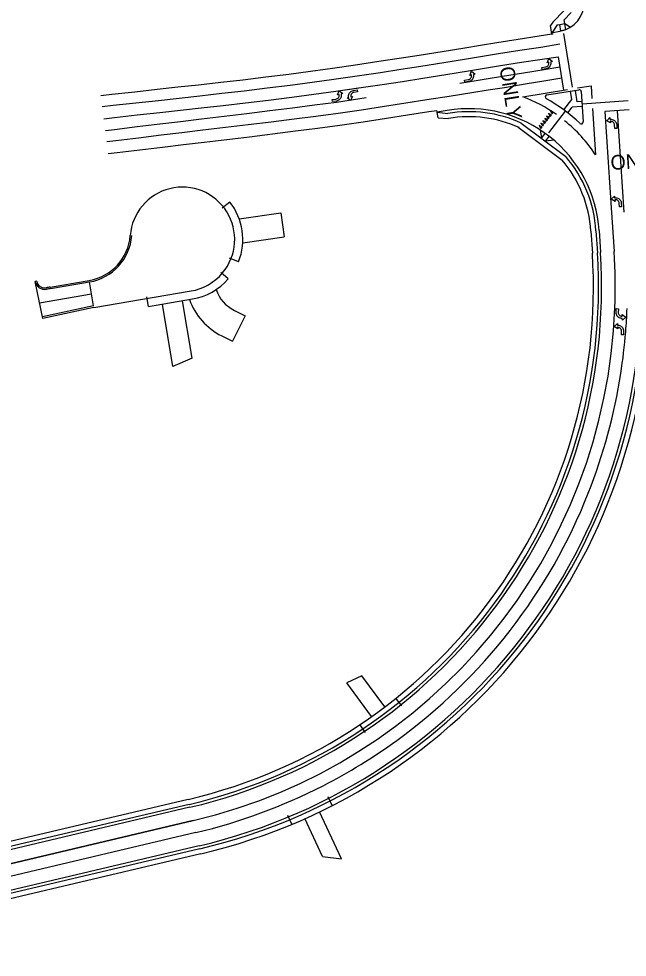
# Model space of a CAD drawing. Extents: x 979036 to 996074, y 1836928 to 1845163.
# Drawn here: x 982073 to 982672, y 1841767 to 1842691 of the extents above; entities that cross this region are included whole.
import ezdxf

# ---------------------------------------------------------------- set-up
doc = ezdxf.new("R2010")
doc.units = 0
for name, color, linetype in [('R_Proposed Road', 7, 'Continuous'), ('STRIPE_White Crosswalk', 7, 'Continuous'), ('STRIPE_White Stopbar', 7, 'Continuous'), ('STRIPE_White Turn Arrow', 7, 'Continuous'), ('STRIPE_WHITE_10_30 SKIP', 7, 'Continuous'), ('STRIPE_White_6in', 7, 'Continuous'), ('STRIPE_White_Dashed', 7, 'Continuous'), ('STRIPE_White_ONLY', 7, 'Continuous'), ('STRIPE_White_Yield Tri', 7, 'Continuous'), ('STRIPE_Yellow Dbl 6in', 7, 'Continuous'), ('STRIPE_Yellow_10_30 SKIP', 7, 'Continuous'), ('STRIPE_Yellow_45_Diag_8in', 7, 'Continuous')]:
    doc.layers.add(name, color=color, linetype=linetype)

msp = doc.modelspace()

# ---------------------------------------------------------------- linework, layer by layer
at = {"layer": 'R_Proposed Road'}
for p, q in [((982621.5, 1842711.53), (982599.06, 1842688.03)), ((982616.91, 1842697.36), (982610.13, 1842690.24)), ((982599.06, 1842688.03), (982596.68, 1842684.43)), ((982611.69, 1842680.55), (982610.13, 1842690.24)), ((982598, 1842676.16), (982596.68, 1842684.43)), ((982597.76, 1842677.64), (982598.96, 1842677.84)), ((982603.23, 1842685.27), (982598.22, 1842677.72)), ((982598.96, 1842677.84), (982605.77, 1842678.93)), ((982603.23, 1842685.27), (982605.8, 1842685.68)), ((982605.8, 1842685.68), (982610.74, 1842686.47)), ((982606.85, 1842679.13), (982605.8, 1842685.68)), ((982606.75, 1842679.76), (982611.69, 1842680.55)), ((982610.74, 1842686.47), (982616.37, 1842682.91)), ((982598, 1842676.16), (982599.19, 1842676.35)), ((982593.23, 1842616.23), (982624.7, 1842621.27)), ((982617.66, 1842611.73), (982616.34, 1842619.93)), ((982623.07, 1842609.57), (982621.28, 1842620.72)), ((982627.01, 1842619.43), (982628.95, 1842589.81)), ((982609.69, 1842601.57), (982617.66, 1842611.73)), ((982613.68, 1842598.55), (982618.14, 1842604.24)), ((982627.96, 1842604.88), (982618.14, 1842604.24)), ((982627.64, 1842609.87), (982623.07, 1842609.57)), ((982485.98, 1842593.61), (982484.81, 1842600.89)), ((982494.95, 1842600.89), (982485.05, 1842599.39)), ((982485.05, 1842599.39), (982495.45, 1842597.93)), ((982485.98, 1842593.61), (982496.28, 1842593)), ((982567.88, 1842588.55), (982611.69, 1842555.65)), ((982564.88, 1842584.55), (982608.24, 1842551.99)), ((982586.54, 1842581.74), (982587.79, 1842573.6)), ((982587.79, 1842573.6), (982591.49, 1842578.33)), ((982591.79, 1842570.6), (982595.49, 1842575.32)), ((982600.12, 1842571.51), (982591.79, 1842570.6)), ((982280.91, 1842510.72), (982273.45, 1842504.84)), ((982290.11, 1842494.19), (982330.98, 1842500.16)), ((982330.98, 1842500.16), (982334.45, 1842476.41)), ((982293.58, 1842470.44), (982334.45, 1842476.41)), ((982636.48, 1842482.02), (982637.89, 1842460.45)), ((982641.47, 1842482.34), (982642.88, 1842460.77)), ((982644.47, 1842482.54), (982645.88, 1842460.97)), ((982289.49, 1842451.97), (982280.66, 1842455.47)), ((982279.28, 1842435.09), (982272.08, 1842441.29)), ((982090.73, 1842432.69), (982089.26, 1842432.39)), ((982096.68, 1842396.14), (982089.26, 1842432.39)), ((982090.76, 1842432.58), (982090.73, 1842432.69)), ((982104.07, 1842427.01), (982142.55, 1842433.53)), ((982104.32, 1842425.54), (982142.8, 1842432.05)), ((982146.81, 1842408.39), (982142.8, 1842432.05)), ((982147.06, 1842406.91), (982242.77, 1842423.12)), ((982200.73, 1842407.88), (982199.14, 1842417.25)), ((982200.73, 1842407.88), (982244.11, 1842415.23)), ((982224.92, 1842348.88), (982214.53, 1842410.22)), ((982243.86, 1842356.83), (982234.25, 1842413.56)), ((982146.81, 1842408.39), (982096.38, 1842397.61)), ((982147.12, 1842406.92), (982096.69, 1842396.14)), ((982285.41, 1842403.98), (982295.95, 1842398.76)), ((982295.95, 1842398.76), (982283.51, 1842373.67)), ((982272.97, 1842378.9), (982283.51, 1842373.67)), ((982243.86, 1842356.83), (982224.92, 1842348.88)), ((982410.97, 1842044.14), (982396.28, 1842037.11)), ((982433.45, 1842013.45), (982410.97, 1842044.14)), ((982420.54, 1842004), (982396.28, 1842037.11)), ((982450.12, 1842014.38), (982444.5, 1842022.05)), ((982414.63, 1841988.38), (982409.01, 1841996.05)), ((982239.83, 1841922.37), (981808.02, 1841820.47)), ((982381.78, 1841916.37), (982377.78, 1841924.99)), ((982240.98, 1841917.5), (981809.17, 1841815.6)), ((982241.67, 1841914.58), (981809.86, 1841812.68)), ((982341.87, 1841897.86), (982337.87, 1841906.48)), ((982372.01, 1841866.14), (982354.72, 1841903.41)), ((982390.77, 1841863.72), (982369.24, 1841910.15)), ((982250.63, 1841876.63), (981818.82, 1841774.72)), ((982251.32, 1841873.71), (981819.5, 1841771.8)), ((982252.47, 1841868.84), (981820.65, 1841766.94)), ((982372.01, 1841866.14), (982390.77, 1841863.72))]:
    msp.add_line(p, q, dxfattribs=at)
for centre, radius, start, end in [((982601.25, 1842707.07), 28.5, 279.12753, 3.73532), ((982593.55, 1842614.25), 2, 99.11059, 241.10715), ((982625.02, 1842619.3), 2, 3.73532, 99.11059), ((982516.24, 1842474.17), 158, 46.21643, 61.10715), ((982516.24, 1842474.17), 128.5, 3.73532, 99.53629), ((982516.24, 1842474.17), 125.5, 65.70107, 99.53629), ((982516.24, 1842474.17), 120.5, 65.70107, 99.53629), ((982626.95, 1842589.68), 2, 226.21643, 3.73532), ((982516.24, 1842474.17), 120.5, 3.73532, 40.22822), ((982516.24, 1842474.17), 125.5, 3.73532, 40.48819), ((982234.18, 1842473.89), 51.5, 320.1465, 175.72415), ((982234.18, 1842473.89), 59.5, 338.38202, 38.24074), ((982134.45, 1842481.35), 48.5, 279.61069, 355.72415), ((982134.45, 1842481.35), 50, 279.61069, 355.72415), ((982120.82, 1842426.69), 518.17, 283.27832, 3.73532), ((982120.82, 1842426.69), 523.17, 283.27832, 3.73532), ((982120.82, 1842426.69), 526.17, 283.27832, 3.73532), ((982120.82, 1842426.69), 565.17, 283.27832, 3.73532), ((982120.82, 1842426.69), 568.17, 283.27832, 3.73532), ((982120.82, 1842426.69), 573.17, 283.27832, 3.73532), ((982234.18, 1842473.89), 51.5, 279.61069, 320.1465), ((982098.59, 1842434.18), 9.5, 191.55654, 280.20735), ((982098.59, 1842434.18), 8, 191.55654, 280.20735), ((982234.18, 1842473.89), 59.5, 279.61069, 319.29798), ((982170.09, 1842037.09), 395.47, 99.61069, 100.20735), ((982170.09, 1842037.09), 393.97, 99.61069, 100.20735), ((982301.4, 1842436.24), 36, 199.00806, 243.62815), ((982301.4, 1842436.24), 64, 199.6413, 243.62815)]:
    msp.add_arc(centre, radius, start, end, dxfattribs=at)
at = {"layer": 'STRIPE_White Crosswalk'}
for p, q in [((982618.24, 1842623.89), (982609.78, 1842676.65)), ((982673.08, 1842610.34), (982627.82, 1842607.14)), ((982595.13, 1842578.93), (982611.45, 1842600.26))]:
    msp.add_line(p, q, dxfattribs=at)
at = {"layer": 'STRIPE_White Stopbar'}
for p, q in [((982604.32, 1842653.88), (982609.61, 1842620.88)), ((982674.29, 1842601.39), (982650.34, 1842599.83))]:
    msp.add_line(p, q, dxfattribs=at)
at = {"layer": 'STRIPE_White Turn Arrow'}
for points in [[(982593.34, 1842647.95), (982595.05, 1842651.97), (982598.5, 1842649.3), (982596.88, 1842648.88), (982596.99, 1842648.22), (982597.05, 1842647.65), (982597.01, 1842646.83), (982596.8, 1842645.84), (982596.51, 1842645.05), (982596.06, 1842644.38), (982595.55, 1842643.6), (982594.94, 1842643.09), (982594.27, 1842642.55), (982593.38, 1842642.13), (982592.44, 1842641.83), (982588.58, 1842641.27), (982588.28, 1842643.25), (982591.84, 1842643.8), (982592.51, 1842643.96), (982593.2, 1842644.29), (982593.91, 1842644.79), (982594.45, 1842645.45), (982594.62, 1842645.78), (982594.89, 1842646.45), (982595.01, 1842647.24), (982595.01, 1842647.99), (982594.95, 1842648.37)], [(982517.2, 1842635.45), (982518.9, 1842639.47), (982522.35, 1842636.8), (982520.74, 1842636.38), (982520.85, 1842635.72), (982520.91, 1842635.14), (982520.87, 1842634.33), (982520.66, 1842633.34), (982520.36, 1842632.55), (982519.92, 1842631.88), (982519.41, 1842631.09), (982518.79, 1842630.59), (982518.12, 1842630.05), (982517.24, 1842629.63), (982516.29, 1842629.32), (982512.43, 1842628.77), (982512.14, 1842630.75), (982515.69, 1842631.29), (982516.36, 1842631.45), (982517.05, 1842631.79), (982517.76, 1842632.28), (982518.31, 1842632.95), (982518.48, 1842633.28), (982518.75, 1842633.95), (982518.87, 1842634.74), (982518.86, 1842635.48), (982518.81, 1842635.87)], [(982386.95, 1842616.32), (982388.7, 1842620.31), (982392.12, 1842617.61), (982390.5, 1842617.2), (982390.6, 1842616.54), (982390.65, 1842615.97), (982390.61, 1842615.15), (982390.38, 1842614.17), (982390.08, 1842613.38), (982389.63, 1842612.71), (982389.11, 1842611.93), (982388.49, 1842611.44), (982387.82, 1842610.9), (982386.92, 1842610.5), (982385.98, 1842610.2), (982382.11, 1842609.69), (982381.84, 1842611.67), (982385.39, 1842612.18), (982386.07, 1842612.33), (982386.76, 1842612.66), (982387.48, 1842613.14), (982388.03, 1842613.8), (982388.2, 1842614.13), (982388.48, 1842614.8), (982388.61, 1842615.59), (982388.61, 1842616.33), (982388.56, 1842616.72)], [(982401.57, 1842614.59), (982399.81, 1842610.6), (982396.4, 1842613.33), (982398.02, 1842613.72), (982397.92, 1842614.38), (982397.87, 1842614.96), (982397.92, 1842615.78), (982398.15, 1842616.76), (982398.46, 1842617.54), (982398.91, 1842618.21), (982399.44, 1842618.99), (982400.06, 1842619.48), (982400.74, 1842620.01), (982401.63, 1842620.41), (982402.58, 1842620.7), (982406.45, 1842621.2), (982406.71, 1842619.21), (982403.15, 1842618.72), (982402.47, 1842618.57), (982401.78, 1842618.25), (982401.06, 1842617.77), (982400.51, 1842617.11), (982400.33, 1842616.78), (982400.05, 1842616.12), (982399.92, 1842615.33), (982399.91, 1842614.58), (982399.96, 1842614.2)], [(982655.85, 1842588.58), (982652.02, 1842590.66), (982655, 1842593.84), (982655.27, 1842592.2), (982655.93, 1842592.24), (982656.51, 1842592.24), (982657.32, 1842592.13), (982658.28, 1842591.83), (982659.04, 1842591.46), (982659.67, 1842590.95), (982660.4, 1842590.37), (982660.84, 1842589.71), (982661.32, 1842588.99), (982661.65, 1842588.07), (982661.87, 1842587.1), (982662.05, 1842583.2), (982660.05, 1842583.1), (982659.85, 1842586.69), (982659.75, 1842587.37), (982659.49, 1842588.09), (982659.06, 1842588.84), (982658.45, 1842589.45), (982658.13, 1842589.65), (982657.5, 1842589.98), (982656.72, 1842590.18), (982655.98, 1842590.24), (982655.59, 1842590.22)], [(982660.41, 1842511.35), (982656.57, 1842513.43), (982659.56, 1842516.61), (982659.82, 1842514.97), (982660.49, 1842515.02), (982661.07, 1842515.02), (982661.88, 1842514.9), (982662.84, 1842514.6), (982663.6, 1842514.23), (982664.23, 1842513.72), (982664.96, 1842513.14), (982665.4, 1842512.48), (982665.88, 1842511.76), (982666.21, 1842510.84), (982666.42, 1842509.87), (982666.61, 1842505.97), (982664.61, 1842505.87), (982664.4, 1842509.46), (982664.31, 1842510.14), (982664.04, 1842510.86), (982663.62, 1842511.62), (982663, 1842512.22), (982662.69, 1842512.42), (982662.05, 1842512.75), (982661.28, 1842512.95), (982660.53, 1842513.01), (982660.14, 1842513)], [(982667.13, 1842399.8), (982670.75, 1842397.36), (982667.47, 1842394.48), (982667.37, 1842396.15), (982666.7, 1842396.16), (982666.12, 1842396.22), (982665.33, 1842396.41), (982664.4, 1842396.81), (982663.68, 1842397.25), (982663.11, 1842397.81), (982662.43, 1842398.46), (982662.06, 1842399.16), (982661.65, 1842399.92), (982661.41, 1842400.87), (982661.29, 1842401.86), (982661.49, 1842405.76), (982663.49, 1842405.66), (982663.35, 1842402.07), (982663.37, 1842401.38), (982663.57, 1842400.64), (982663.92, 1842399.85), (982664.47, 1842399.19), (982664.76, 1842398.96), (982665.36, 1842398.57), (982666.12, 1842398.3), (982666.85, 1842398.16), (982667.24, 1842398.14)], [(982662.87, 1842385.7), (982659.24, 1842388.12), (982662.51, 1842391.02), (982662.62, 1842389.35), (982663.29, 1842389.34), (982663.87, 1842389.29), (982664.66, 1842389.1), (982665.59, 1842388.71), (982666.31, 1842388.27), (982666.89, 1842387.71), (982667.57, 1842387.06), (982667.94, 1842386.36), (982668.36, 1842385.61), (982668.6, 1842384.66), (982668.72, 1842383.67), (982668.55, 1842379.77), (982666.55, 1842379.85), (982666.67, 1842383.45), (982666.64, 1842384.14), (982666.45, 1842384.88), (982666.09, 1842385.67), (982665.54, 1842386.32), (982665.24, 1842386.55), (982664.64, 1842386.94), (982663.88, 1842387.21), (982663.15, 1842387.34), (982662.76, 1842387.36)]]:
    msp.add_lwpolyline(points, close=True, dxfattribs=at)
at = {"layer": 'STRIPE_WHITE_10_30 SKIP'}
msp.add_lwpolyline([(982607.71, 1842632.68), (982592.2, 1842630.18), (982571.76, 1842626.78), (982551.24, 1842623.36), (982535.19, 1842620.83), (982519.2, 1842618.31), (982497.03, 1842614.79), (982474.85, 1842611.27), (982454.08, 1842608.03), (982433.31, 1842604.79), (982410.44, 1842601.36), (982387.5, 1842597.92), (982365.75, 1842595.12), (982344.1, 1842592.33), (982321.54, 1842589.5), (982298.95, 1842586.66), (982276.57, 1842584.03), (982254.25, 1842581.41), (982233.77, 1842578.94), (982213.27, 1842576.47), (982191, 1842573.77), (982168.7, 1842571.07), (982159.63, 1842570.02)], dxfattribs=at)
at = {"layer": 'STRIPE_White_6in'}
for p, q in [((982623.43, 1842623.09), (982636.66, 1842625.22)), ((982636.66, 1842625.22), (982637.46, 1842612.83)), ((982569.4, 1842614.43), (982613.56, 1842621.51)), ((982638.12, 1842602.85), (982641.09, 1842557.31)), ((982662.31, 1842600.61), (982668.83, 1842500.82))]:
    msp.add_line(p, q, dxfattribs=at)
for points in [[(982153.93, 1842615.59), (982164.74, 1842616.95), (982187.23, 1842619.39), (982209.49, 1842621.81), (982229.8, 1842624.05), (982250.11, 1842626.3), (982271.95, 1842628.73), (982293.63, 1842631.14), (982316.21, 1842633.97), (982338.85, 1842636.81), (982360.42, 1842639.71), (982381.94, 1842642.6), (982404.66, 1842645.96), (982427.52, 1842649.34), (982447.54, 1842652.33), (982467.47, 1842655.31), (982489.88, 1842658.89), (982512.27, 1842662.48), (982527.88, 1842665.17), (982543.85, 1842667.92), (982564.8, 1842671.12), (982585.43, 1842674.26), (982597.98, 1842676.28)], [(982605.97, 1842643.54), (982590.42, 1842641.04), (982569.95, 1842637.63), (982549.48, 1842634.22), (982533.48, 1842631.7), (982517.48, 1842629.18), (982507.25, 1842627.55)], [(982156.81, 1842592.77), (982167.42, 1842594.11), (982189.71, 1842596.53), (982212, 1842598.94), (982232.32, 1842601.19), (982252.65, 1842603.44), (982274.49, 1842605.87), (982296.34, 1842608.3), (982319.07, 1842611.15), (982341.81, 1842614), (982363.48, 1842616.91), (982385.15, 1842619.83), (982405.95, 1842622.9)], [(982415.18, 1842613.2), (982408.81, 1842612.24), (982385.98, 1842608.82), (982364.35, 1842606.03), (982342.71, 1842603.24), (982320.17, 1842600.41), (982297.63, 1842597.57), (982275.29, 1842594.95), (982252.95, 1842592.33), (982232.45, 1842589.86), (982211.96, 1842587.39), (982189.68, 1842584.69), (982167.41, 1842582), (982158.36, 1842580.94)], [(982484.84, 1842600.7), (982476.71, 1842599.41), (982455.93, 1842596.17), (982435.12, 1842592.93), (982412.22, 1842589.5), (982389.15, 1842586.04), (982367.29, 1842583.22), (982345.62, 1842580.43), (982323.04, 1842577.59), (982300.4, 1842574.74), (982277.97, 1842572.11), (982255.67, 1842569.49), (982235.21, 1842567.02), (982214.71, 1842564.55), (982192.44, 1842561.86), (982170.12, 1842559.16), (982161.02, 1842558.1)]]:
    msp.add_lwpolyline(points, dxfattribs=at)
for start, end in [(54.8488, 69.24225), (33.66175, 51.07187)]:
    msp.add_arc((982516.24, 1842474.17), 150, start, end, dxfattribs=at)
at = {"layer": 'STRIPE_White_Dashed'}
msp.add_lwpolyline([(982155.31, 1842604.67), (982166.02, 1842606.03), (982188.42, 1842608.46), (982210.69, 1842610.87), (982231, 1842613.12), (982251.33, 1842615.36), (982273.17, 1842617.79), (982294.93, 1842620.22), (982317.58, 1842623.06), (982340.27, 1842625.9), (982361.89, 1842628.81), (982383.48, 1842631.71), (982406.27, 1842635.08), (982429.13, 1842638.46), (982449.17, 1842641.45), (982469.15, 1842644.44), (982491.62, 1842648.03), (982514.08, 1842651.62), (982529.75, 1842654.33), (982545.61, 1842657.06), (982566.45, 1842660.24), (982587.13, 1842663.39), (982605.87, 1842666.41)], dxfattribs=at)
at = {"layer": 'STRIPE_White_Yield Tri'}
for p, q in [((982595.76, 1842594.32), (982592.82, 1842595.43)), ((982592.82, 1842595.43), (982594.52, 1842592.74)), ((982594.52, 1842592.74), (982595.76, 1842594.32)), ((982597.61, 1842596.68), (982594.67, 1842597.79)), ((982594.67, 1842597.79), (982596.37, 1842595.1)), ((982596.37, 1842595.1), (982597.61, 1842596.68)), ((982599.46, 1842599.04), (982596.52, 1842600.15)), ((982596.52, 1842600.15), (982598.22, 1842597.46)), ((982598.22, 1842597.46), (982599.46, 1842599.04)), ((982588.36, 1842584.87), (982585.42, 1842585.98)), ((982585.42, 1842585.98), (982587.12, 1842583.29)), ((982590.21, 1842587.23), (982587.27, 1842588.35)), ((982587.27, 1842588.35), (982588.97, 1842585.66)), ((982588.97, 1842585.66), (982590.21, 1842587.23)), ((982592.06, 1842589.59), (982589.12, 1842590.71)), ((982589.12, 1842590.71), (982590.82, 1842588.02)), ((982590.82, 1842588.02), (982592.06, 1842589.59)), ((982593.91, 1842591.95), (982590.97, 1842593.07)), ((982590.97, 1842593.07), (982592.67, 1842590.38)), ((982592.67, 1842590.38), (982593.91, 1842591.95)), ((982587.12, 1842583.29), (982588.36, 1842584.87))]:
    msp.add_line(p, q, dxfattribs=at)
at = {"layer": 'STRIPE_Yellow Dbl 6in'}
for p, q in [((982650.34, 1842599.83), (982656.85, 1842500.04)), ((982656.52, 1842505.13), (982659.35, 1842461.85)), ((982093.58, 1842411.32), (982144.8, 1842420.22))]:
    msp.add_line(p, q, dxfattribs=at)
msp.add_lwpolyline([(982406.72, 1842623.01), (982408.03, 1842623.21), (982430.9, 1842626.59), (982450.94, 1842629.58), (982470.99, 1842632.58), (982493.51, 1842636.18), (982516.04, 1842639.79), (982531.79, 1842642.5), (982547.53, 1842645.22), (982568.26, 1842648.38), (982604.32, 1842653.88)], dxfattribs=at)
msp.add_arc((982120.82, 1842426.69), 539.67, 357.85372, 3.73532, dxfattribs=at)
at = {"layer": 'STRIPE_Yellow_10_30 SKIP'}
for p, q in [((981812.96, 1841799.54), (982244.77, 1841901.44)), ((982244.77, 1841901.44), (981812.96, 1841799.54)), ((982247.53, 1841889.77), (981815.71, 1841787.86)), ((982247.53, 1841889.77), (981815.71, 1841787.86))]:
    msp.add_line(p, q, dxfattribs=at)
for points in [[(982156.81, 1842592.77), (982167.42, 1842594.11), (982189.71, 1842596.53), (982212, 1842598.94), (982232.32, 1842601.19), (982252.65, 1842603.44), (982274.49, 1842605.87), (982296.34, 1842608.3), (982319.07, 1842611.15), (982341.81, 1842614), (982363.48, 1842616.91), (982385.15, 1842619.83), (982407.47, 1842623.13)], [(982409.08, 1842612.28), (982385.98, 1842608.82), (982364.35, 1842606.03), (982342.71, 1842603.24), (982320.17, 1842600.41), (982297.63, 1842597.57), (982275.29, 1842594.95), (982252.95, 1842592.33), (982232.45, 1842589.86), (982211.96, 1842587.39), (982189.68, 1842584.69), (982167.41, 1842582), (982158.36, 1842580.94)]]:
    msp.add_lwpolyline(points, dxfattribs=at)
for radius, start, end in [(539.67, 283.27832, 357.85371), (539.67, 283.27832, 357.85371), (551.67, 355.44704, 357.85372), (551.67, 355.44704, 357.85372), (551.67, 351.14942, 355.44704), (551.67, 351.14942, 355.44704), (551.67, 338.45128, 351.14983), (551.67, 338.45128, 351.14983), (551.67, 306.02462, 338.45128), (551.67, 306.02462, 338.45128), (551.67, 297.16489, 306.02257), (551.67, 297.16489, 306.02257), (551.67, 283.27832, 297.16489), (551.67, 283.27832, 297.16489)]:
    msp.add_arc((982120.82, 1842426.69), radius, start, end, dxfattribs=at)
at = {"layer": 'STRIPE_Yellow_45_Diag_8in'}
for p, q in [((982451.61, 1842629.35), (982451.86, 1842629.16)), ((982660.24, 1842451.79), (982660.37, 1842451.93))]:
    msp.add_line(p, q, dxfattribs=at)

# ---------------------------------------------------------------- texts
at = {"layer": 'STRIPE_White_ONLY'}
for rotation, p in [(279.11059, (982546.42, 1842643.03)), (3.73532, (982656.22, 1842542.27))]:
    msp.add_text('ONLY', height=14.4, rotation=rotation, dxfattribs=at).set_placement(p)

doc.saveas('drawing.dxf')
